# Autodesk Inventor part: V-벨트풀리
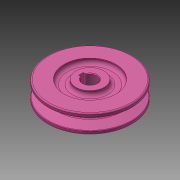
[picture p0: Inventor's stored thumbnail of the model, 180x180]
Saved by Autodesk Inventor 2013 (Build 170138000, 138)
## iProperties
Created: 2015-12
Part Number: V-벨트풀리
Material: 강철, 연강
Document SubType Name: Modeling
Designer: mdu
Density: 7.86 g/cm^3
CustomPartVersion: 1
Author: mdu
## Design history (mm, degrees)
sketch "주 스케치"
  geometry: L1 (0, 16)-(35.7, 16); L2 (35.7, 16)-(35.7, 12.825); L3 (35.7, 12.825)-(26.7, 10.074); L4 (26.7, 10.074)-(26.7, 5.926); L5 (26.7, 5.926)-(35.7, 3.175); L6 (35.7, 3.175)-(35.7, 0); L7 (35.7, 0)-(0, 0); L8 (33, 12)-(33, 4); L9 (26.7, 8)-(33, 8); L10 (35.7, 12.825)-(35.7, 3.175); L11 (0, -3.2)-(0, 19.2) reference; L12 (0, 0)-(0, 16)
  constraints: 22 end point, 5 perpendicular, 2 collinear, 2 midpoint, 2 point on line, 1 parallel
  dimensions: "d0" = 8 distance of L8.start L8.end (= da_Bw); "d1" = 34 deg angle of L3 L5 (= da_Alfa); "d2" = 2.7 distance between parallel lines of L2 L8 (= da_c); "d6" = 16 distance between parallel lines of L7 L1 (computed from d5, da_ng, da_Sg); "d21" = 66 diameter of L8 L11; "d25" = 9 distance between parallel lines of L4 L10 (= da_Hd); "d27" = 8 distance between parallel lines of L7 L9 (= da_Se)
node "벨트 평면"
revolve "본체" stored, may be unused: angle "d7" = 90 deg
revolve "그루브" stored, may be unused: angle "d15" = 90 deg
feature "허브 키홈"
fillet "모깎기3" dims "d28" = 0.5, "d29" = 1, "d30" = 1
sketch "스케치2"
  geometry: C1 r 12 at (0, 0); C2 r 25 at (0, 0); 1 further point
  constraints: 2 centre point, 2 coincident
  dimensions: "d31" = 24 diameter of C1; "d32" = 50 diameter of C2
extrude "돌출1" cut sketch "스케치2" distance "d33" = 4; taper "d34" = 0 deg
node "작업 평면2"
fillet "모깎기4" dims "d35" = 3, "d39" = 2
chamfer "모따기1" distance "d36" = 0.5; stored, may be unused: second distance "d37" = 2, angle "d38" = 45 deg
body "Solid1"
pattern_linear "그루브 패턴" dims "d18" = 12 (= da_Sg)
mirror "대칭1"
other parameters: "d5" = 8 (= da_Se), "da_Bw" = 8 [user parameter; used in 1 equation term], "da_Alfa" = 34 deg [user parameter; used in 1 equation term], "da_c" = 2.7 [user parameter; used in 1 equation term], "da_Dw" = 64 [user parameter], "da_Hd" = 9 (computed from d2) [user parameter; used in 1 equation term], "da_Se" = 8 [user parameter; used in 2 equation terms], "da_Sg" = 12 [user parameter; used in 2 equation terms], "da_r1" = 0 [user parameter], "da_r2" = 0 [user parameter], "d24" = 0, "d26" = 0
